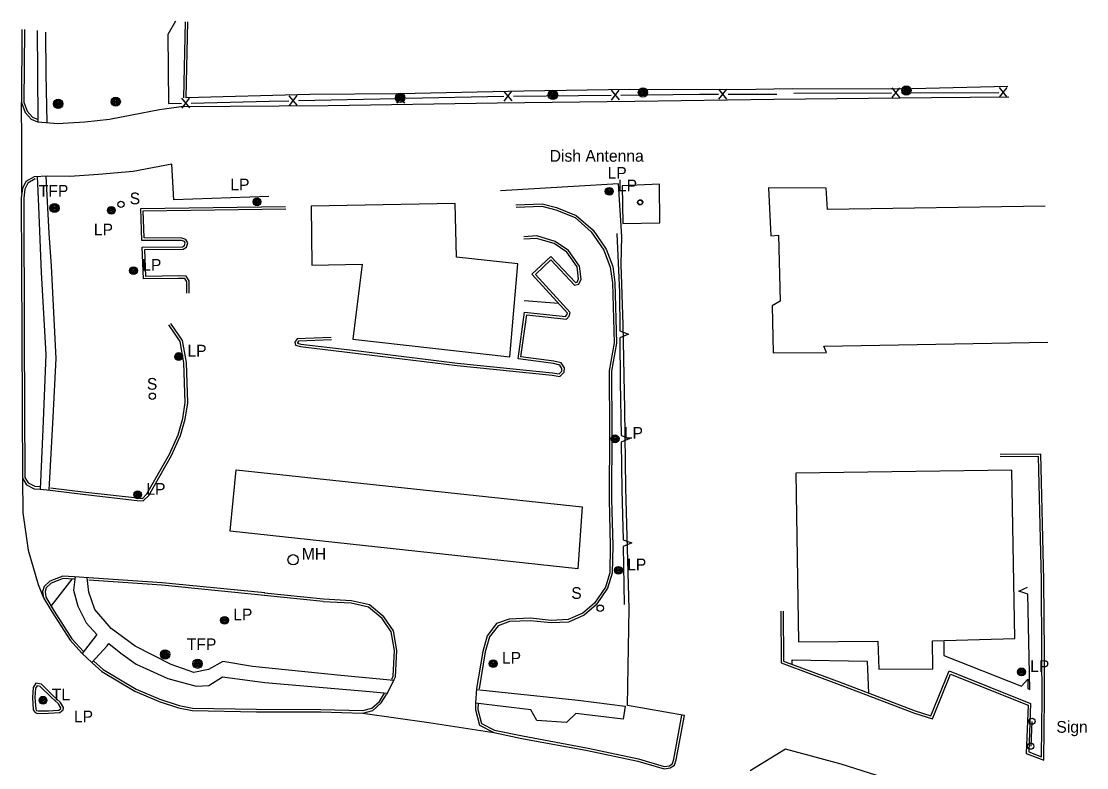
# Model space of a CAD drawing. Extents: x 2402803 to 2427059, y 6985292 to 6997652.
# Drawn here: x 2426562.8 to 2426999.1, y 6991847.7 to 6992153.5 of the extents above; entities that cross this region are included whole.
import ezdxf

# ---------------------------------------------------------------- set-up
doc = ezdxf.new("R2010")
doc.units = 0
for name, color, linetype in [('p_dtm retaining wall', 7, 'Continuous'), ('p_dtm sidewalk', 7, 'Continuous'), ('p_road - paved curb', 7, 'Continuous'), ('p_structure building', 7, 'Continuous'), ('p_structure fence', 7, 'Continuous'), ('p_structure general', 7, 'Continuous'), ('p_structure sign', 7, 'Continuous'), ('p_utility manhole', 7, 'Continuous')]:
    doc.layers.add(name, color=color, linetype=linetype)

msp = doc.modelspace()

# ---------------------------------------------------------------- linework, layer by layer
at = {"layer": 'p_dtm retaining wall'}
msp.add_line((2426809.27, 6991938.32), (2426809.76, 6991914.58), dxfattribs=at)
for points in [[(2426806.73, 6992066.59), (2426807.77, 6992042.38), (2426807.87, 6992026.61)], [(2426807.87, 6992026.61), (2426811.51, 6992025.32), (2426807.89, 6992023.84)], [(2426807.89, 6992023.84), (2426808.01, 6992005.67), (2426808.4, 6991983.85)], [(2426808.4, 6991983.85), (2426812.05, 6991982.59), (2426808.45, 6991981.08)], [(2426808.45, 6991981.08), (2426808.8, 6991961.45), (2426809.22, 6991941.09)], [(2426809.22, 6991941.09), (2426812.87, 6991939.85), (2426809.27, 6991938.32)], [(2426974.98, 6991918.83), (2426971.32, 6991920.07), (2426974.92, 6991921.6)], [(2426974.99, 6991880.11), (2426975.86, 6991879.77), (2426974.98, 6991918.83)], [(2426940.61, 6991899.44), (2426940.65, 6991893.59), (2426972.42, 6991881.12)], [(2426972.42, 6991881.12), (2426974.97, 6991884.02), (2426975, 6991880.11)]]:
    msp.add_lwpolyline(points, dxfattribs=at)
at = {"layer": 'p_dtm sidewalk'}
for points in [[(2426569.73, 6992112.25), (2426569.49, 6992132.63), (2426569.37, 6992149.69)], [(2426573.38, 6992111.98), (2426572.91, 6992132.03), (2426572.76, 6992149.04)], [(2426569.2, 6992089.88), (2426569.88, 6992077.59), (2426570.85, 6992050.57), (2426572.88, 6992016.93), (2426571.56, 6991986.42), (2426570.53, 6991961.83)], [(2426574.23, 6991961.43), (2426575.86, 6991991.26), (2426577.08, 6992015.37), (2426575.1, 6992053.14), (2426574.2, 6992066.69), (2426572.94, 6992090.05)], [(2426782.83, 6992037.85), (2426768.74, 6992038.93)], [(2426584.83, 6991925.86), (2426584.14, 6991920.37), (2426585.9, 6991913.91), (2426589.37, 6991907.1), (2426593.76, 6991902.25), (2426587.69, 6991894.51)], [(2426575, 6991913.9), (2426583.61, 6991924.93)], [(2426715.33, 6991883.44), (2426693.61, 6991885.43), (2426657.5, 6991889.16), (2426645.33, 6991891.15), (2426639.39, 6991887.9), (2426633.44, 6991886.75), (2426624.2, 6991889.95), (2426609.42, 6991897.47), (2426599.6, 6991904.77), (2426592.86, 6991912.55), (2426590.37, 6991919.6), (2426589.79, 6991925.53)], [(2426591.71, 6991890.73), (2426597.98, 6991897.57), (2426598.63, 6991898.51), (2426603.57, 6991894.61), (2426609.79, 6991890.05), (2426622.77, 6991884.26), (2426634.39, 6991881.04), (2426639.54, 6991881.32), (2426645.23, 6991884.86), (2426662.52, 6991882.53), (2426705.46, 6991878.92), (2426712.6, 6991878.17)], [(2426878.54, 6991889.98), (2426878.57, 6991891.83), (2426909.29, 6991891.39), (2426909.75, 6991878.23)], [(2426749.23, 6991879.77), (2426790.81, 6991875.35), (2426810.06, 6991872.87), (2426809.3, 6991867.51), (2426789.91, 6991869.91), (2426786.04, 6991866.24), (2426773.99, 6991867.02), (2426771.43, 6991871.43), (2426748.86, 6991874.17)]]:
    msp.add_lwpolyline(points, dxfattribs=at)
at = {"layer": 'p_road - paved curb'}
for points in [[(2426629.36, 6992122.14), (2426630.04, 6992153.31)], [(2426630.36, 6992122.12), (2426631.04, 6992153.29)], [(2426563.01, 6992150.12), (2426562.85, 6992120.24), (2426564.3, 6992116.09), (2426566.8, 6992113.34), (2426569.43, 6992112.27), (2426569.57, 6992112.26)], [(2426564.01, 6992150.11), (2426563.85, 6992120.41), (2426565.18, 6992116.61), (2426567.39, 6992114.18), (2426569.66, 6992113.26), (2426569.66, 6992113.26)], [(2426966.78, 6992126.77), (2426922.1, 6992125.71), (2426878.57, 6992125.76), (2426856.08, 6992125.44), (2426811.86, 6992125.53), (2426768.54, 6992124.9), (2426717.74, 6992123.73), (2426681, 6992123.46), (2426630.36, 6992122.12)], [(2426569.57, 6992112.26), (2426577.77, 6992111.65), (2426588.8, 6992112.31), (2426598.87, 6992113.44), (2426608.08, 6992115.14), (2426619.35, 6992117.35), (2426628.22, 6992118.6), (2426688.46, 6992119.02), (2426757.73, 6992120.04), (2426814.09, 6992120.72), (2426870.99, 6992121.63), (2426935.53, 6992122.22), (2426967.27, 6992122.52)], [(2426562.99, 6992083.06), (2426563.01, 6992103.51), (2426562.85, 6992120.24)], [(2426664.11, 6992081.73), (2426625.22, 6992080.41), (2426624.37, 6992094.98), (2426608.56, 6992091.89), (2426594.38, 6992090.69), (2426582.65, 6992089.84), (2426573.66, 6992090.08), (2426568.01, 6992089.83)], [(2426568.01, 6992089.83), (2426564.67, 6992087.92), (2426563.21, 6992084.99), (2426562.77, 6992081.14), (2426563, 6992024.33), (2426563.22, 6991966.35), (2426564.9, 6991963.6), (2426567.98, 6991961.99), (2426570.53, 6991961.83)], [(2426568.51, 6992088.96), (2426565.43, 6992087.2), (2426564.18, 6992084.7), (2426563.77, 6992081.09), (2426564, 6992024.33), (2426564.22, 6991966.63), (2426565.61, 6991964.36), (2426568.25, 6991962.97), (2426570.59, 6991962.83)], [(2426834.36, 6991869.03), (2426811.07, 6991873.21), (2426811.75, 6991912.81), (2426810.35, 6991962.32), (2426809.97, 6991994.57), (2426809.25, 6992029.15), (2426808.53, 6992054.03), (2426808.68, 6992065.38), (2426807.41, 6992086.9), (2426759.11, 6992084.05)], [(2426765.37, 6992078.35), (2426776.04, 6992078.74), (2426782, 6992077.14), (2426790.1, 6992073.9), (2426796.95, 6992067.85), (2426802.26, 6992060.14), (2426805, 6992053.06), (2426805.88, 6992046.45), (2426806.6, 6992021.63), (2426804.51, 6992010.15), (2426804.66, 6991985.87), (2426804.5, 6991957.6), (2426804.99, 6991938.59), (2426804.82, 6991927.32), (2426802.92, 6991921.25), (2426798.28, 6991914.37), (2426793.36, 6991910.13), (2426786.92, 6991907.37), (2426779.8, 6991907.04), (2426771.24, 6991907.89), (2426762.72, 6991907.52), (2426758.08, 6991905.86), (2426754.47, 6991901.29), (2426752.73, 6991895.11), (2426750.25, 6991880.01)], [(2426630.58, 6992042.13), (2426630.55, 6992046.81), (2426629.74, 6992048.14), (2426627.13, 6992048.16), (2426612.76, 6992047.96), (2426612.29, 6992060.98), (2426628.83, 6992061.1), (2426629.57, 6992061.58), (2426629.93, 6992062.64), (2426629.55, 6992063.28), (2426628.32, 6992063.69), (2426612.17, 6992063.72), (2426611.68, 6992076.81), (2426671.04, 6992077.65)], [(2426631.58, 6992042.14), (2426631.55, 6992047.09), (2426630.31, 6992049.13), (2426627.13, 6992049.16), (2426613.72, 6992048.97), (2426613.33, 6992059.99), (2426629.13, 6992060.1), (2426630.41, 6992060.93), (2426631.02, 6992062.75), (2426630.22, 6992064.11), (2426628.48, 6992064.69), (2426613.13, 6992064.72), (2426612.72, 6992075.82), (2426671.05, 6992076.65)], [(2426765.41, 6992077.35), (2426775.93, 6992077.74), (2426781.68, 6992076.19), (2426789.57, 6992073.04), (2426796.2, 6992067.18), (2426801.37, 6992059.67), (2426804.02, 6992052.81), (2426804.88, 6992046.37), (2426805.6, 6992021.71), (2426803.51, 6992010.24), (2426803.66, 6991985.87), (2426803.5, 6991957.59), (2426803.99, 6991938.58), (2426803.82, 6991927.48), (2426802.01, 6991921.69), (2426797.53, 6991915.04), (2426792.82, 6991910.99), (2426786.69, 6991908.36), (2426779.83, 6991908.04), (2426771.27, 6991908.89), (2426762.53, 6991908.51), (2426757.47, 6991906.71), (2426753.56, 6991901.75), (2426751.75, 6991895.33), (2426749.26, 6991880.17)], [(2426689.73, 6992023.92), (2426675.81, 6992023.42), (2426674.76, 6992022), (2426675.11, 6992020.84), (2426677.1, 6992020.29), (2426700.71, 6992017.42), (2426741.35, 6992012.4), (2426780.18, 6992008.48), (2426783.37, 6992007.91), (2426785.14, 6992009.72), (2426785.19, 6992011.53), (2426783.92, 6992013.54), (2426780.87, 6992014.25), (2426767.39, 6992016.05), (2426769.77, 6992033.23), (2426786.03, 6992031.51), (2426787.11, 6992032.67), (2426787.55, 6992034.16), (2426773.32, 6992049.77), (2426779.6, 6992055.72), (2426789.35, 6992045.38), (2426791.16, 6992045.73), (2426792.05, 6992047.86), (2426791.46, 6992053.2), (2426786.89, 6992059.6), (2426781.45, 6992063.32), (2426773.92, 6992065.53), (2426768.6, 6992065.23)], [(2426689.77, 6992022.92), (2426676.33, 6992022.44), (2426675.86, 6992021.81), (2426675.91, 6992021.66), (2426677.29, 6992021.27), (2426700.83, 6992018.41), (2426741.46, 6992013.39), (2426780.32, 6992009.47), (2426783.02, 6992008.99), (2426784.15, 6992010.14), (2426784.18, 6992011.25), (2426783.29, 6992012.66), (2426780.69, 6992013.27), (2426766.26, 6992015.19), (2426768.91, 6992034.33), (2426785.64, 6992032.56), (2426786.22, 6992033.18), (2426786.43, 6992033.9), (2426771.92, 6992049.82), (2426779.64, 6992057.14), (2426789.7, 6992046.47), (2426790.44, 6992046.61), (2426791.03, 6992048.01), (2426790.49, 6992052.83), (2426786.18, 6992058.87), (2426781.02, 6992062.41), (2426773.8, 6992064.52), (2426768.66, 6992064.23)], [(2426574.63, 6991961.39), (2426589.12, 6991959.63), (2426610.28, 6991957.21), (2426612.73, 6991957.01), (2426615.03, 6991959.24), (2426624.35, 6991975.64), (2426627.97, 6991983.75), (2426629.9, 6991990.5), (2426630.92, 6991997.21), (2426630.4, 6992013.68), (2426628.76, 6992022.7), (2426624, 6992029.69)], [(2426574.75, 6991962.38), (2426589.24, 6991960.62), (2426610.38, 6991958.21), (2426612.36, 6991958.04), (2426614.23, 6991959.86), (2426623.46, 6991976.09), (2426627.03, 6991984.09), (2426628.92, 6991990.71), (2426629.92, 6991997.27), (2426629.4, 6992013.57), (2426627.81, 6992022.31), (2426623.17, 6992029.13)], [(2426873.81, 6991911.83), (2426874, 6991890.61), (2426898.88, 6991881.31), (2426928.56, 6991869.98), (2426935.92, 6991867.76), (2426943.4, 6991886.03), (2426975.14, 6991873.29), (2426974.39, 6991853.51), (2426981.64, 6991850.71), (2426981.86, 6991876.14), (2426981.83, 6991894.5), (2426981.62, 6991924.6), (2426980.41, 6991976.14), (2426963.69, 6991976.04)], [(2426874.81, 6991911.84), (2426874.99, 6991891.31), (2426899.23, 6991882.25), (2426928.88, 6991870.93), (2426935.34, 6991868.98), (2426942.85, 6991887.33), (2426976.17, 6991873.96), (2426975.42, 6991854.19), (2426980.65, 6991852.16), (2426980.86, 6991876.14), (2426980.83, 6991894.5), (2426980.62, 6991924.58), (2426979.43, 6991975.13), (2426963.7, 6991975.04)], [(2426563.22, 6991966.35), (2426563.46, 6991952.07), (2426565.53, 6991936.79), (2426569.65, 6991922.78), (2426571.87, 6991917.21)], [(2426570.53, 6991961.83), (2426574.63, 6991961.39)], [(2426584.51, 6991925.88), (2426584.42, 6991925.89), (2426579.73, 6991926.17), (2426574.45, 6991924.09), (2426572.1, 6991921.95), (2426571.51, 6991919.91), (2426571.87, 6991917.21), (2426575.35, 6991911.35), (2426582.74, 6991899.91), (2426587.53, 6991894.66)], [(2426590.47, 6991925.48), (2426584.42, 6991925.89)], [(2426584.4, 6991924.89), (2426584.33, 6991924.89), (2426579.89, 6991925.16), (2426574.99, 6991923.23), (2426572.98, 6991921.4), (2426572.53, 6991919.83), (2426572.83, 6991917.54), (2426576.2, 6991911.88), (2426583.53, 6991900.52), (2426588.27, 6991895.33)], [(2426662.38, 6991918.29), (2426620.35, 6991922.44), (2426590.4, 6991924.48)], [(2426662.48, 6991919.29), (2426620.43, 6991923.44), (2426590.47, 6991925.48)], [(2426686.39, 6991915.71), (2426662.28, 6991918.24)], [(2426686.49, 6991916.7), (2426662.38, 6991919.23)], [(2426714.5, 6991884), (2426715.07, 6991885.13), (2426715.62, 6991895.68), (2426714.3, 6991903.4), (2426710.54, 6991908.81), (2426704.95, 6991913.46), (2426697.93, 6991915.1), (2426686.44, 6991915.7)], [(2426715.39, 6991883.55), (2426716.06, 6991884.87), (2426716.62, 6991895.74), (2426715.25, 6991903.79), (2426711.28, 6991909.49), (2426705.41, 6991914.38), (2426698.07, 6991916.09), (2426686.49, 6991916.7)], [(2426587.53, 6991894.66), (2426591.83, 6991890.62)], [(2426592.5, 6991891.36), (2426596.32, 6991887.88), (2426609.77, 6991879.89), (2426619.55, 6991875.75), (2426627.38, 6991873.22), (2426632.93, 6991872.12), (2426659.12, 6991871.6), (2426685.45, 6991871.55), (2426702.59, 6991871.06), (2426706.31, 6991872.07), (2426709.45, 6991874.87), (2426711.47, 6991878.15)], [(2426591.83, 6991890.62), (2426595.72, 6991887.07), (2426609.32, 6991879), (2426619.2, 6991874.81), (2426627.13, 6991872.25), (2426632.82, 6991871.12), (2426659.11, 6991870.6), (2426685.43, 6991870.55), (2426702.71, 6991870.06), (2426706.8, 6991871.17), (2426710.23, 6991874.22), (2426712.32, 6991877.63)], [(2426575.68, 6991877.27), (2426571.04, 6991881.9), (2426568.76, 6991882.26), (2426567.59, 6991880.58), (2426567.32, 6991876.4), (2426567.69, 6991871.39), (2426568.41, 6991870.26), (2426569.5, 6991869.94), (2426573.86, 6991870.03)], [(2426715.39, 6991883.55), (2426712.32, 6991877.63)], [(2426574.97, 6991876.56), (2426570.56, 6991880.96), (2426569.22, 6991881.17), (2426568.57, 6991880.24), (2426568.32, 6991876.4), (2426568.67, 6991871.71), (2426569.05, 6991871.11), (2426569.63, 6991870.94), (2426573.84, 6991871.03)], [(2426749.26, 6991880.17), (2426748.86, 6991874.17)], [(2426573.81, 6991871.03), (2426578.2, 6991871.27), (2426578.98, 6991871.92), (2426578.99, 6991872.15), (2426578.04, 6991873.78), (2426575.01, 6991876.53)], [(2426573.86, 6991870.03), (2426578.59, 6991870.29), (2426579.95, 6991871.43), (2426580.01, 6991872.39), (2426578.83, 6991874.42), (2426575.68, 6991877.27)], [(2426748.86, 6991874.17), (2426748.74, 6991871.44), (2426750.39, 6991865.16), (2426756.28, 6991862.11), (2426767.82, 6991859.7), (2426794.72, 6991854.66), (2426815.36, 6991850.38), (2426826.03, 6991847.17), (2426828.59, 6991847.56), (2426830.32, 6991848.78), (2426831.04, 6991850.93), (2426834.36, 6991869.03)], [(2426749.86, 6991874.13), (2426749.75, 6991871.55), (2426751.24, 6991865.84), (2426756.62, 6991863.06), (2426768.01, 6991860.68), (2426794.91, 6991855.64), (2426815.61, 6991851.35), (2426826.1, 6991848.19), (2426828.21, 6991848.51), (2426829.48, 6991849.41), (2426830.07, 6991851.18), (2426833.38, 6991869.21)], [(2426702.71, 6991870.06), (2426729.72, 6991866.15), (2426756.28, 6991862.11)], [(2426992.48, 6991798.2), (2426992.21, 6991809.11), (2426986.36, 6991821.82), (2426960.37, 6991830.37), (2426932.57, 6991838.28), (2426898.56, 6991849.11), (2426875.81, 6991855.34), (2426861.35, 6991846.36)]]:
    msp.add_lwpolyline(points, dxfattribs=at)
at = {"layer": 'p_structure building'}
msp.add_lwpolyline([(2426982.12, 6992077.74), (2426892.95, 6992076.4), (2426892.4, 6992085.15), (2426868.84, 6992085.29), (2426869.81, 6992065.55), (2426872.96, 6992065.93), (2426873.57, 6992038.8), (2426870.29, 6992036.89), (2426870.78, 6992017.69), (2426892.52, 6992017.85), (2426891.53, 6992020.39), (2426983.23, 6992022.09)], dxfattribs=at)
for points in [[(2426740.52, 6992078.89), (2426681.55, 6992077.68), (2426681.77, 6992053.64), (2426702.41, 6992054), (2426698.59, 6992023.29), (2426762.84, 6992015.96), (2426766.14, 6992054.13), (2426740.98, 6992056.79)], [(2426650.78, 6991969.77), (2426792.51, 6991954.55), (2426790.69, 6991929.12), (2426648.37, 6991944.55)], [(2426968.46, 6991969.57), (2426879.95, 6991968.36), (2426881.08, 6991899.19), (2426913.62, 6991899.51), (2426914, 6991888.01), (2426936.18, 6991888.22), (2426936, 6991899.63), (2426969.66, 6991900.65)]]:
    msp.add_lwpolyline(points, close=True, dxfattribs=at)
at = {"layer": 'p_structure fence'}
for p, q in [((2426675.8, 6992119.07), (2426672.52, 6992123.01)), ((2426672.6, 6992119.01), (2426675.72, 6992123.07)), ((2426719.79, 6992119.97), (2426716.51, 6992123.9)), ((2426716.59, 6992119.9), (2426719.71, 6992123.96)), ((2426720.35, 6992121.95), (2426760.34, 6992122.76)), ((2426763.77, 6992120.86), (2426760.49, 6992124.79)), ((2426760.58, 6992120.79), (2426763.69, 6992124.86)), ((2426764.34, 6992122.81), (2426804.33, 6992123.21)), ((2426807.75, 6992121.28), (2426804.51, 6992125.24)), ((2426804.55, 6992121.24), (2426807.71, 6992125.27)), ((2426851.73, 6992121.64), (2426848.52, 6992125.63)), ((2426848.53, 6992121.63), (2426851.72, 6992125.64)), ((2426852.32, 6992123.61), (2426872.25, 6992123.67)), ((2426879.23, 6992124.08), (2426919.23, 6992124.21)), ((2426922.63, 6992122.25), (2426919.42, 6992126.24)), ((2426919.43, 6992122.24), (2426922.62, 6992126.25)), ((2426923.22, 6992124.22), (2426963.22, 6992124.35)), ((2426966.63, 6992122.39), (2426963.41, 6992126.38)), ((2426963.43, 6992122.38), (2426966.61, 6992126.39)), ((2426631.83, 6992118.02), (2426628.53, 6992121.94)), ((2426628.63, 6992117.94), (2426631.72, 6992122.02)), ((2426676.36, 6992121.05), (2426716.35, 6992121.87))]:
    msp.add_line(p, q, dxfattribs=at)
for points in [[(2426625.93, 6992153.49), (2426622.72, 6992148.07), (2426623.01, 6992119.77), (2426628.38, 6992119.91)], [(2426808.33, 6992123.25), (2426840.49, 6992123.57), (2426848.33, 6992123.59)], [(2426632.38, 6992120.01), (2426664.34, 6992120.81), (2426672.36, 6992120.97)], [(2426824.32, 6992070.96), (2426824.18, 6992086.78), (2426808.86, 6992086.02)], [(2426808.86, 6992086.02), (2426809.17, 6992070.7), (2426824.35, 6992070.96)]]:
    msp.add_lwpolyline(points, dxfattribs=at)
at = {"layer": 'p_structure general'}
for centre in [(2426816.19, 6992079.22), (2426816.3, 6992079.36)]:
    msp.add_circle(centre, 1, dxfattribs=at)
at = {"layer": 'p_structure sign'}
msp.add_line((2426976.73, 6991866.67), (2426976.2, 6991856.53), dxfattribs=at)
for centre in [(2426603.6, 6992078.53), (2426616.41, 6991999.89), (2426799.88, 6991913.02), (2426976.74, 6991866.66), (2426976.21, 6991856.52)]:
    msp.add_circle(centre, 1.3, dxfattribs=at)
at = {"layer": 'p_utility manhole'}
for centre, radius in [((2426925.28, 6992125.15), 1.9), ((2426925.28, 6992125.15), 1.44), ((2426601.43, 6992120.56), 1.9), ((2426717.93, 6992122.17), 1.9), ((2426717.93, 6992122.17), 1.44), ((2426717.93, 6992122.17), 0.973), ((2426717.93, 6992122.17), 0.539), ((2426717.93, 6992122.17), 0.192), ((2426780.51, 6992123.35), 1.9), ((2426780.51, 6992123.35), 1.44), ((2426780.51, 6992123.35), 0.973), ((2426780.51, 6992123.35), 0.539), ((2426780.51, 6992123.35), 0.192), ((2426817.39, 6992124.35), 1.9), ((2426817.39, 6992124.35), 1.44), ((2426817.39, 6992124.35), 0.973), ((2426817.39, 6992124.35), 0.539), ((2426817.39, 6992124.35), 0.192), ((2426925.28, 6992125.15), 0.973), ((2426925.28, 6992125.15), 0.539), ((2426925.28, 6992125.15), 0.192), ((2426577.87, 6992119.66), 1.9), ((2426577.87, 6992119.66), 1.44), ((2426577.87, 6992119.66), 0.973), ((2426577.87, 6992119.66), 0.539), ((2426577.87, 6992119.66), 0.192), ((2426601.43, 6992120.56), 1.44), ((2426601.43, 6992120.56), 0.973), ((2426601.43, 6992120.56), 0.539), ((2426601.43, 6992120.56), 0.192), ((2426803.58, 6992083.83), 1.6), ((2426803.58, 6992083.8), 1.6), ((2426803.58, 6992083.83), 1.3), ((2426803.58, 6992083.8), 1.3), ((2426803.58, 6992083.83), 1), ((2426803.58, 6992083.8), 1), ((2426803.58, 6992083.83), 0.539), ((2426803.58, 6992083.8), 0.539), ((2426803.58, 6992083.83), 0.192), ((2426803.58, 6992083.8), 0.192), ((2426576.37, 6992076.99), 1.9), ((2426659.31, 6992079.52), 1.6), ((2426659.31, 6992079.52), 1.3), ((2426659.31, 6992079.52), 1), ((2426659.31, 6992079.52), 0.539), ((2426659.31, 6992079.52), 0.192), ((2426576.37, 6992076.99), 1.44), ((2426576.37, 6992076.99), 0.973), ((2426576.37, 6992076.99), 0.539), ((2426576.37, 6992076.99), 0.192), ((2426599.66, 6992076.06), 1.6), ((2426599.66, 6992076.06), 1.3), ((2426599.66, 6992076.06), 1), ((2426599.66, 6992076.06), 0.539), ((2426599.66, 6992076.06), 0.192), ((2426608.72, 6992051.31), 1.6), ((2426608.72, 6992051.31), 1.3), ((2426608.72, 6992051.31), 1), ((2426608.72, 6992051.31), 0.539), ((2426608.72, 6992051.31), 0.192), ((2426627.26, 6992016.14), 1.6), ((2426627.26, 6992016.14), 1.3), ((2426627.26, 6992016.14), 1), ((2426627.26, 6992016.14), 0.539), ((2426627.26, 6992016.14), 0.192), ((2426805.99, 6991982.45), 1.6), ((2426805.99, 6991982.45), 1.3), ((2426805.99, 6991982.45), 1), ((2426805.99, 6991982.45), 0.539), ((2426805.99, 6991982.45), 0.192), ((2426610.42, 6991959.49), 1.6), ((2426610.42, 6991959.49), 1.3), ((2426610.42, 6991959.49), 1), ((2426610.42, 6991959.49), 0.539), ((2426610.42, 6991959.49), 0.192), ((2426674.08, 6991932.89), 2.1), ((2426807.35, 6991928.55), 1.6), ((2426807.35, 6991928.55), 1.3), ((2426807.35, 6991928.55), 1), ((2426807.35, 6991928.55), 0.539), ((2426807.35, 6991928.55), 0.192), ((2426646.01, 6991908.06), 1.6), ((2426646.01, 6991908.06), 1.3), ((2426646.01, 6991908.06), 1), ((2426646.01, 6991908.06), 0.539), ((2426646.01, 6991908.06), 0.192), ((2426621.66, 6991894.08), 1.9), ((2426621.66, 6991894.08), 1.44), ((2426621.66, 6991894.08), 0.973), ((2426621.66, 6991894.08), 0.539), ((2426621.66, 6991894.08), 0.192), ((2426634.97, 6991890.28), 1.9), ((2426634.97, 6991890.28), 1.44), ((2426634.97, 6991890.28), 0.973), ((2426756.06, 6991890.29), 1.6), ((2426756.06, 6991890.29), 1.3), ((2426756.06, 6991890.29), 1), ((2426634.97, 6991890.28), 0.539), ((2426634.97, 6991890.28), 0.192), ((2426756.06, 6991890.29), 0.539), ((2426756.06, 6991890.29), 0.192), ((2426972.43, 6991886.92), 1.6), ((2426972.43, 6991886.92), 1.3), ((2426972.43, 6991886.92), 1), ((2426972.43, 6991886.92), 0.539), ((2426972.43, 6991886.92), 0.192), ((2426571.68, 6991875.31), 1.6), ((2426571.68, 6991875.31), 1.3), ((2426571.68, 6991875.31), 1), ((2426571.68, 6991875.31), 0.539), ((2426571.68, 6991875.31), 0.192)]:
    msp.add_circle(centre, radius, dxfattribs=at)

# ---------------------------------------------------------------- texts
at = {"layer": 'p_structure general'}
msp.add_text('Dish Antenna', height=4.8, dxfattribs=at).set_placement((2426779.19, 6992095.96))
at = {"layer": 'p_structure sign'}
for s, p in [('  S', (2426603.59, 6992078.52)), ('  S', (2426610.64, 6992002.55)), ('  S', (2426784.46, 6991916.85)), ('Sign', (2426986.71, 6991862.01))]:
    msp.add_text(s, height=4.8, dxfattribs=at).set_placement(p)
at = {"layer": 'p_utility manhole'}
for s, p in [('  LP', (2426799.33, 6992088.99)), ('  LP', (2426644.83, 6992084.2)), ('  LP', (2426803.58, 6992083.8)), ('  TFP', (2426566.35, 6992081.65)), ('  LP', (2426588.92, 6992065.78)), ('  LP', (2426608.72, 6992051.31)), ('  LP', (2426627.26, 6992016.14)), ('  LP', (2426805.99, 6991982.45)), ('  LP', (2426610.42, 6991959.49)), ('  MH', (2426674.08, 6991932.89)), ('  LP', (2426807.35, 6991928.55)), ('  LP', (2426646.01, 6991908.06)), ('  TFP', (2426626.99, 6991895.85)), ('  LP', (2426756.06, 6991890.29)), ('  LP', (2426972.43, 6991886.92)), ('  TL', (2426571.68, 6991875.31)), ('LP', (2426584.31, 6991866.27))]:
    msp.add_text(s, height=4.8, dxfattribs=at).set_placement(p)

doc.saveas('drawing.dxf')
